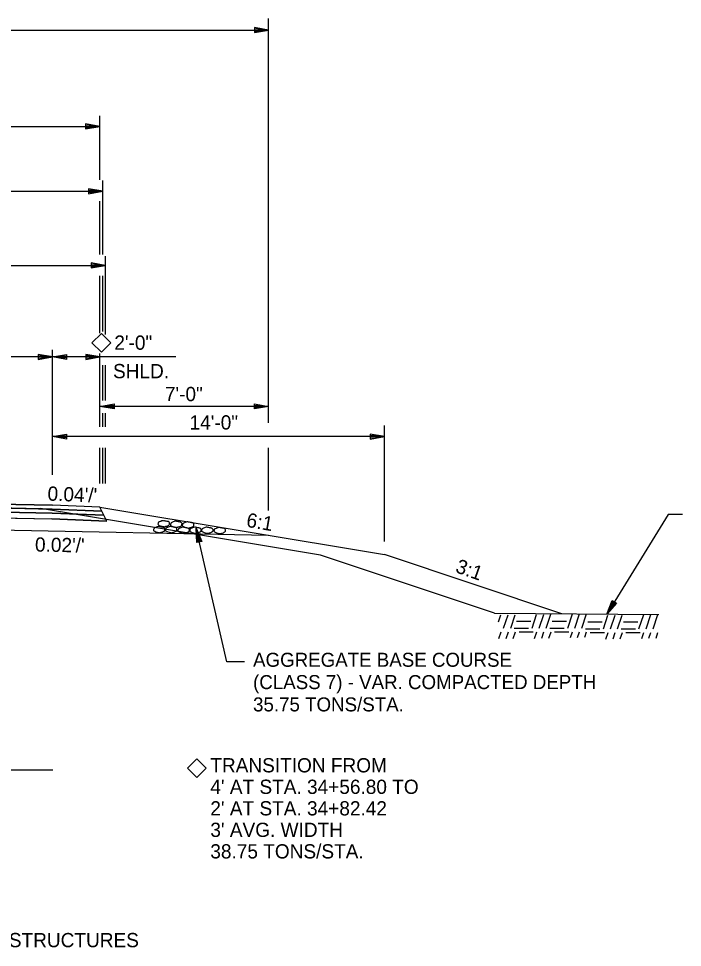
# Model space of a CAD drawing. Extents: x 1461570 to 1461697, y 1686711 to 1686957.
# Drawn here: x 1461621.86 to 1461649.85, y 1686718.74 to 1686757.85 of the extents above; entities that cross this region are included whole.
import ezdxf

# ---------------------------------------------------------------- set-up
doc = ezdxf.new("R2010")
doc.units = 0
for name, color, linetype in [('1', 7, 'Continuous'), ('10', 7, 'Continuous'), ('19', 7, 'Continuous'), ('20', 7, 'Continuous'), ('3', 7, 'Continuous'), ('42', 7, 'Continuous'), ('Level 9', 7, 'Continuous'), ('R_Draft', 7, 'Continuous')]:
    doc.layers.add(name, color=color, linetype=linetype)

# ---------------------------------------------------------------- blocks, each defined once
blk = doc.blocks.new('ROCKS')
at = {"layer": '1'}
blk.add_spline([(0.013, 0.06), (0.053, 0.053), (0.107, 0.033), (0.133, 0.013), (0.133, -0.007), (0.12, -0.033), (0.107, -0.04), (0.073, -0.053), (0.033, -0.067), (0.013, -0.067), (-0.02, -0.06), (-0.06, -0.053), (-0.087, -0.047), (-0.113, -0.02), (-0.113, -0.007), (-0.107, 0.02), (-0.087, 0.033), (-0.067, 0.047), (-0.033, 0.053), (-0.02, 0.06), (0.013, 0.06)], degree=3, dxfattribs=at)

msp = doc.modelspace()

# ---------------------------------------------------------------- linework, layer by layer
at = {"layer": '10'}
for points in [[(1461625.352, 1686744.594), (1461625.749, 1686744.196), (1461625.352, 1686743.798), (1461624.954, 1686744.196)], [(1461629.374, 1686726.684), (1461629.771, 1686726.287), (1461629.374, 1686725.889), (1461628.976, 1686726.287)]]:
    msp.add_lwpolyline(points, close=True, dxfattribs=at)
at = {"layer": '19'}
for p, q in [((1461625.285, 1686741.519), (1461625.885, 1686741.624)), ((1461625.885, 1686741.414), (1461625.285, 1686741.519)), ((1461625.445, 1686741.534), (1461625.885, 1686741.569)), ((1461625.885, 1686741.464), (1461625.445, 1686741.504)), ((1461625.885, 1686741.624), (1461625.885, 1686741.414)), ((1461631.801, 1686741.413), (1461631.801, 1686741.623)), ((1461631.801, 1686741.623), (1461632.401, 1686741.519)), ((1461631.801, 1686741.568), (1461632.241, 1686741.534)), ((1461632.401, 1686741.519), (1461631.801, 1686741.413)), ((1461632.241, 1686741.504), (1461631.801, 1686741.463)), ((1461612.285, 1686737.582), (1461623.285, 1686737.362)), ((1461623.285, 1686737.362), (1461612.285, 1686737.582)), ((1461612.285, 1686737.582), (1461623.285, 1686737.362)), ((1461612.285, 1686737.416), (1461622.202, 1686737.217)), ((1461612.285, 1686737.416), (1461623.28, 1686737.196)), ((1461612.285, 1686737.249), (1461623.275, 1686737.029)), ((1461625.37, 1686737.112), (1461623.28, 1686737.196)), ((1461625.285, 1686737.282), (1461623.285, 1686737.362)), ((1461625.285, 1686737.282), (1461623.285, 1686737.362)), ((1461625.285, 1686737.282), (1461623.285, 1686737.362)), ((1461625.285, 1686737.282), (1461637.285, 1686735.282)), ((1461625.37, 1686737.112), (1461625.285, 1686737.282)), ((1461625.58, 1686736.687), (1461625.285, 1686737.282)), ((1461612.285, 1686736.999), (1461623.268, 1686736.779)), ((1461625.58, 1686736.687), (1461623.268, 1686736.779)), ((1461625.454, 1686736.942), (1461623.275, 1686737.029)), ((1461612.285, 1686736.499), (1461632.401, 1686736.097)), ((1461630.645, 1686730.763), (1461629.348, 1686736.391)), ((1461629.378, 1686735.784), (1461629.348, 1686736.391)), ((1461629.348, 1686736.391), (1461629.582, 1686735.828)), ((1461629.427, 1686735.795), (1461629.367, 1686736.232)), ((1461629.395, 1686736.238), (1461629.53, 1686735.82)), ((1461629.582, 1686735.828), (1461629.378, 1686735.784)), ((1461644.766, 1686732.789), (1461637.285, 1686735.282)), ((1461646.664, 1686732.772), (1461646.887, 1686733.339)), ((1461647.065, 1686733.229), (1461646.664, 1686732.772)), ((1461646.737, 1686732.913), (1461646.93, 1686733.306)), ((1461647.024, 1686733.25), (1461646.76, 1686732.902)), ((1461646.887, 1686733.339), (1461647.065, 1686733.229)), ((1461641.925, 1686732.814), (1461648.855, 1686732.753)), ((1461631.382, 1686730.763), (1461630.645, 1686730.763))]:
    msp.add_line(p, q, dxfattribs=at)
for points in [[(1461612.285, 1686737.249), (1461623.275, 1686737.029), (1461625.454, 1686736.942), (1461625.37, 1686737.112), (1461623.28, 1686737.196), (1461612.285, 1686737.416)], [(1461612.285, 1686736.999), (1461623.268, 1686736.779), (1461625.58, 1686736.687), (1461625.454, 1686736.942), (1461623.275, 1686737.029), (1461612.285, 1686737.249)], [(1461622.202, 1686737.217), (1461623.28, 1686737.196), (1461625.37, 1686737.112)], [(1461625.285, 1686737.282), (1461625.285, 1686737.282)], [(1461649.846, 1686736.971), (1461649.246, 1686736.971), (1461646.664, 1686732.772)]]:
    msp.add_lwpolyline(points, dxfattribs=at)
at = {"layer": '20'}
for p, q in [((1461632.401, 1686740.83), (1461632.401, 1686757.853)), ((1461631.801, 1686757.47), (1461631.801, 1686757.26)), ((1461632.401, 1686757.365), (1461631.801, 1686757.47)), ((1461592.17, 1686757.365), (1461632.401, 1686757.365)), ((1461632.241, 1686757.38), (1461631.801, 1686757.415)), ((1461631.801, 1686757.26), (1461632.401, 1686757.365)), ((1461631.801, 1686757.31), (1461632.241, 1686757.35)), ((1461625.285, 1686751.061), (1461625.285, 1686753.763)), ((1461599.285, 1686753.31), (1461625.285, 1686753.31)), ((1461624.685, 1686753.415), (1461624.685, 1686753.205)), ((1461625.285, 1686753.31), (1461624.685, 1686753.415)), ((1461625.125, 1686753.325), (1461624.685, 1686753.36)), ((1461624.685, 1686753.205), (1461625.285, 1686753.31)), ((1461624.685, 1686753.255), (1461625.125, 1686753.295)), ((1461625.412, 1686747.913), (1461625.412, 1686751.036)), ((1461599.159, 1686750.582), (1461625.412, 1686750.582)), ((1461624.812, 1686750.687), (1461624.812, 1686750.477)), ((1461625.412, 1686750.582), (1461624.812, 1686750.687)), ((1461625.252, 1686750.597), (1461624.812, 1686750.632)), ((1461624.812, 1686750.477), (1461625.412, 1686750.582)), ((1461624.812, 1686750.527), (1461625.252, 1686750.567)), ((1461625.285, 1686747.913), (1461625.285, 1686750.162)), ((1461625.517, 1686747.845), (1461625.517, 1686744.55)), ((1461599.054, 1686747.459), (1461625.517, 1686747.459)), ((1461624.917, 1686747.564), (1461624.917, 1686747.354)), ((1461625.517, 1686747.459), (1461624.917, 1686747.564)), ((1461625.357, 1686747.474), (1461624.917, 1686747.509)), ((1461624.917, 1686747.354), (1461625.517, 1686747.459)), ((1461624.917, 1686747.404), (1461625.357, 1686747.444)), ((1461625.285, 1686744.609), (1461625.285, 1686747.013)), ((1461625.412, 1686744.673), (1461625.412, 1686747.013)), ((1461623.285, 1686738.637), (1461623.285, 1686743.906)), ((1461622.685, 1686743.711), (1461622.685, 1686743.501)), ((1461623.285, 1686743.606), (1461622.685, 1686743.711)), ((1461623.125, 1686743.621), (1461622.685, 1686743.656)), ((1461622.685, 1686743.501), (1461623.285, 1686743.606)), ((1461622.685, 1686743.551), (1461623.125, 1686743.591)), ((1461623.285, 1686743.606), (1461623.885, 1686743.711)), ((1461623.885, 1686743.501), (1461623.285, 1686743.606)), ((1461623.445, 1686743.621), (1461623.885, 1686743.656)), ((1461623.885, 1686743.551), (1461623.445, 1686743.591)), ((1461623.885, 1686743.711), (1461623.885, 1686743.501)), ((1461624.691, 1686743.712), (1461624.691, 1686743.502)), ((1461625.291, 1686743.607), (1461624.691, 1686743.712)), ((1461625.131, 1686743.622), (1461624.691, 1686743.657)), ((1461624.691, 1686743.502), (1461625.291, 1686743.607)), ((1461624.691, 1686743.552), (1461625.131, 1686743.592)), ((1461625.285, 1686740.655), (1461625.285, 1686743.743)), ((1461625.412, 1686741.775), (1461625.412, 1686743.254)), ((1461625.517, 1686743.254), (1461625.517, 1686741.775)), ((1461625.285, 1686741.88), (1461625.285, 1686742.834)), ((1461625.285, 1686741.643), (1461625.285, 1686742.834)), ((1461625.412, 1686740.655), (1461625.412, 1686741.238)), ((1461625.517, 1686741.238), (1461625.517, 1686740.655)), ((1461637.285, 1686735.837), (1461637.285, 1686740.719)), ((1461623.285, 1686740.246), (1461623.885, 1686740.351)), ((1461623.885, 1686740.141), (1461623.285, 1686740.246)), ((1461623.445, 1686740.261), (1461623.885, 1686740.296)), ((1461623.885, 1686740.191), (1461623.445, 1686740.231)), ((1461623.885, 1686740.351), (1461623.885, 1686740.141)), ((1461636.685, 1686740.351), (1461636.685, 1686740.141)), ((1461637.285, 1686740.246), (1461636.685, 1686740.351)), ((1461637.125, 1686740.261), (1461636.685, 1686740.296)), ((1461636.685, 1686740.141), (1461637.285, 1686740.246)), ((1461636.685, 1686740.191), (1461637.125, 1686740.231)), ((1461625.285, 1686738.276), (1461625.285, 1686739.774)), ((1461625.412, 1686738.276), (1461625.412, 1686739.774)), ((1461625.517, 1686739.774), (1461625.517, 1686738.276)), ((1461632.401, 1686737.131), (1461632.401, 1686739.774))]:
    msp.add_line(p, q, dxfattribs=at)
at = {"layer": '3'}
msp.add_line((1461601.3, 1686726.22), (1461623.3, 1686726.22), dxfattribs=at)
at = {"layer": '42'}
for p, q in [((1461624.285, 1686743.606), (1461612.285, 1686743.607)), ((1461628.493, 1686743.607), (1461623.28, 1686743.606)), ((1461637.285, 1686740.246), (1461623.285, 1686740.246)), ((1461642.095, 1686732.442), (1461642.197, 1686732.748)), ((1461642.308, 1686732.181), (1461642.496, 1686732.745)), ((1461642.608, 1686732.181), (1461642.795, 1686732.743)), ((1461642.858, 1686732.481), (1461643.458, 1686732.481)), ((1461643.508, 1686732.181), (1461643.698, 1686732.753)), ((1461643.808, 1686732.181), (1461644, 1686732.759)), ((1461644.108, 1686732.181), (1461644.302, 1686732.765)), ((1461644.358, 1686732.481), (1461644.958, 1686732.481)), ((1461645.008, 1686732.181), (1461645.208, 1686732.781)), ((1461645.054, 1686732.781), (1461645.058, 1686732.781)), ((1461645.308, 1686732.181), (1461645.508, 1686732.781)), ((1461645.608, 1686732.181), (1461645.808, 1686732.781)), ((1461645.863, 1686732.45), (1461646.463, 1686732.45)), ((1461646.513, 1686732.15), (1461646.704, 1686732.722)), ((1461646.813, 1686732.15), (1461647.006, 1686732.728)), ((1461647.113, 1686732.15), (1461647.308, 1686732.735)), ((1461647.363, 1686732.45), (1461647.963, 1686732.45)), ((1461648.013, 1686732.15), (1461648.213, 1686732.75)), ((1461648.06, 1686732.75), (1461648.063, 1686732.75)), ((1461648.313, 1686732.15), (1461648.513, 1686732.75)), ((1461648.613, 1686732.15), (1461648.813, 1686732.75)), ((1461642.113, 1686731.748), (1461642.208, 1686732.031)), ((1461642.413, 1686731.746), (1461642.508, 1686732.031)), ((1461642.712, 1686731.744), (1461642.808, 1686732.031)), ((1461642.758, 1686732.181), (1461643.358, 1686732.181)), ((1461642.958, 1686732.031), (1461643.558, 1686732.031)), ((1461643.614, 1686731.751), (1461643.708, 1686732.031)), ((1461643.916, 1686731.757), (1461644.008, 1686732.031)), ((1461644.219, 1686731.764), (1461644.308, 1686732.031)), ((1461644.258, 1686732.181), (1461644.858, 1686732.181)), ((1461644.458, 1686732.031), (1461645.008, 1686732.031)), ((1461645.008, 1686732.031), (1461645.058, 1686732.031)), ((1461645.125, 1686731.782), (1461645.208, 1686732.031)), ((1461645.427, 1686731.789), (1461645.508, 1686732.031)), ((1461645.729, 1686731.795), (1461645.808, 1686732.031)), ((1461645.763, 1686732.15), (1461646.363, 1686732.15)), ((1461647.263, 1686732.15), (1461647.863, 1686732.15)), ((1461645.963, 1686732), (1461646.563, 1686732)), ((1461646.62, 1686731.72), (1461646.713, 1686732)), ((1461646.922, 1686731.727), (1461647.013, 1686732)), ((1461647.224, 1686731.733), (1461647.313, 1686732)), ((1461647.463, 1686732), (1461648.013, 1686732)), ((1461648.013, 1686732), (1461648.063, 1686732)), ((1461648.13, 1686731.752), (1461648.213, 1686732)), ((1461648.432, 1686731.758), (1461648.513, 1686732)), ((1461648.734, 1686731.764), (1461648.813, 1686732))]:
    msp.add_line(p, q, dxfattribs=at)
at = {"layer": 'Level 9'}
msp.add_line((1461632.401, 1686741.519), (1461625.285, 1686741.519), dxfattribs=at)
at = {"layer": 'R_Draft'}
for p, q in [((1461612.285, 1686737.437), (1461622.785, 1686737.227)), ((1461634.586, 1686735.26), (1461622.785, 1686737.227)), ((1461641.925, 1686732.814), (1461634.586, 1686735.26))]:
    msp.add_line(p, q, dxfattribs=at)

# ---------------------------------------------------------------- block references
at = {"layer": '1', "xscale": 1.968733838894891, "yscale": 1.968733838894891, "rotation": 180}
for p in [(1461627.81, 1686736.325), (1461628.002, 1686736.575), (1461628.309, 1686736.325), (1461628.527, 1686736.548), (1461628.839, 1686736.298), (1461629.026, 1686736.521), (1461629.338, 1686736.298), (1461629.837, 1686736.298), (1461630.362, 1686736.285)]:
    msp.add_blockref('ROCKS', p, dxfattribs=at)

# ---------------------------------------------------------------- texts
at = {"layer": '1'}
msp.add_text('NOTE: SEE BRIDGE LAYOUTS FOR APPROACH SLABS AND BRIDGE STRUCTURES ', height=0.6, dxfattribs=at).set_placement((1461595.012, 1686718.744))
at = {"layer": '19'}
for s, p in [('2\'-0"', (1461625.897, 1686743.906)), ('SHLD.', (1461625.842, 1686742.706)), ('7\'-0"', (1461628.028, 1686741.741)), ('14\'-0"', (1461629.069, 1686740.546))]:
    msp.add_text(s, height=0.6, dxfattribs=at).set_placement(p)
for s, height, rotation, p in [("0.04'/'", 0.6, 357.8398, (1461623.073, 1686737.554)), ('6:1', 0.6, 350.1584, (1461631.432, 1686736.455)), ("0.02'/'", 0.6, 358.8542, (1461622.548, 1686735.408)), ('3:1', 0.6, 340.4943, (1461640.241, 1686734.547)), ('AGGREGATE BASE COURSE', 0.59001, 360, (1461631.745, 1686730.554)), ('(CLASS 7) - VAR. COMPACTED DEPTH', 0.59001, 360, (1461631.745, 1686729.614)), ('35.75 TONS/STA.', 0.59001, 360, (1461631.745, 1686728.674)), ('TRANSITION FROM', 0.6, 359.9954, (1461629.944, 1686726.107)), ("4' AT STA. 34+56.80 TO", 0.6, 359.9954, (1461629.944, 1686725.201)), ("2' AT STA. 34+82.42", 0.6, 359.9954, (1461629.944, 1686724.294)), ("3' AVG. WIDTH", 0.6, 359.9954, (1461629.944, 1686723.388)), ('38.75 TONS/STA.', 0.6, 359.9954, (1461629.944, 1686722.482))]:
    msp.add_text(s, height=height, rotation=rotation, dxfattribs=at).set_placement(p)

doc.saveas('drawing.dxf')
